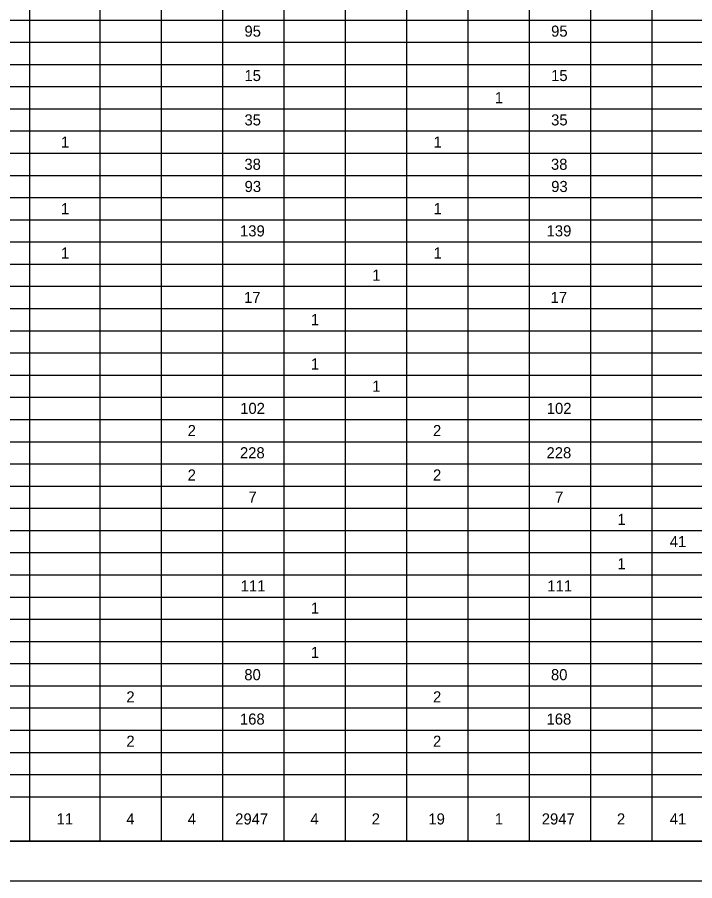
# Model space of a CAD drawing. Extents: x 0 to 34, y 0 to 22.
# Drawn here: x 17.13 to 25.68, y 0 to 10.89 of the extents above; entities that cross this region are included whole.
import ezdxf

# ---------------------------------------------------------------- set-up
doc = ezdxf.new("R2010")
doc.units = 0
for name, color, linetype in [('Default', 7, 'Continuous'), ('SH_Border', 7, 'Continuous'), ('SH_Cut_Line', 7, 'Continuous')]:
    doc.layers.add(name, color=color, linetype=linetype)

msp = doc.modelspace()

# ---------------------------------------------------------------- linework, layer by layer
at = {"layer": 'Default'}
for p, q in [((17.279, 21.5), (17.279, 0.5)), ((18.168, 21.5), (18.168, 0.5)), ((18.942, 21.5), (18.942, 0.5)), ((19.716, 21.5), (19.716, 0.5)), ((20.491, 21.5), (20.491, 0.5)), ((21.265, 21.5), (21.265, 0.5)), ((22.039, 21.5), (22.039, 0.5)), ((22.813, 21.5), (22.813, 0.5)), ((23.587, 21.5), (23.587, 0.5)), ((24.361, 21.5), (24.361, 0.5)), ((25.135, 21.5), (25.135, 0.5)), ((1.5, 10.86), (31.724, 10.86)), ((1.5, 10.58), (31.724, 10.58)), ((1.5, 10.3), (31.724, 10.3)), ((1.5, 10.02), (31.724, 10.02)), ((1.5, 9.74), (31.724, 9.74)), ((1.5, 9.46), (31.724, 9.46)), ((1.5, 9.18), (31.724, 9.18)), ((1.5, 8.9), (31.724, 8.9)), ((1.5, 8.62), (31.724, 8.62)), ((1.5, 8.34), (31.724, 8.34)), ((1.5, 8.06), (31.724, 8.06)), ((1.5, 7.78), (31.724, 7.78)), ((1.5, 7.5), (31.724, 7.5)), ((1.5, 7.22), (31.724, 7.22)), ((1.5, 6.94), (31.724, 6.94)), ((1.5, 6.66), (31.724, 6.66)), ((1.5, 6.38), (31.724, 6.38)), ((1.5, 6.1), (31.724, 6.1)), ((1.5, 5.82), (31.724, 5.82)), ((1.5, 5.54), (31.724, 5.54)), ((1.5, 5.26), (31.724, 5.26)), ((1.5, 4.98), (31.724, 4.98)), ((1.5, 4.7), (31.724, 4.7)), ((1.5, 4.42), (31.724, 4.42)), ((1.5, 4.14), (31.724, 4.14)), ((1.5, 3.86), (31.724, 3.86)), ((1.5, 3.58), (31.724, 3.58)), ((1.5, 3.3), (31.724, 3.3)), ((1.5, 3.02), (31.724, 3.02)), ((1.5, 2.74), (31.724, 2.74)), ((1.5, 2.46), (31.724, 2.46)), ((1.5, 2.18), (31.724, 2.18)), ((1.5, 1.9), (31.724, 1.9)), ((1.5, 1.62), (31.724, 1.62)), ((1.5, 1.34), (31.724, 1.34)), ((1.5, 1.06), (31.724, 1.06)), ((1.5, 0.5), (31.724, 0.5))]:
    msp.add_line(p, q, dxfattribs=at)
at = {"layer": 'SH_Border'}
msp.add_lwpolyline([(1.5, 21.5), (33.5, 21.5), (33.5, 0.5), (1.5, 0.5)], close=True, dxfattribs=at)
at = {"layer": 'SH_Cut_Line'}
msp.add_lwpolyline([(0, 0), (34, 0), (34, 22), (0, 22)], close=True, dxfattribs=at)

# ---------------------------------------------------------------- texts
at = {"layer": 'Default'}
for s, p in [('95', (19.994, 10.65)), ('95', (23.865, 10.65)), ('15', (19.994, 10.09)), ('15', (23.865, 10.09)), ('1', (23.154, 9.81)), ('35', (19.994, 9.53)), ('35', (23.865, 9.53)), ('1', (17.678, 9.25)), ('1', (22.38, 9.25)), ('38', (19.993, 8.97)), ('38', (23.863, 8.97)), ('93', (19.996, 8.69)), ('93', (23.866, 8.69)), ('1', (17.678, 8.41)), ('1', (22.38, 8.41)), ('139', (19.938, 8.13)), ('139', (23.808, 8.13)), ('1', (17.678, 7.85)), ('1', (22.38, 7.85)), ('1', (21.606, 7.57)), ('17', (19.989, 7.29)), ('17', (23.859, 7.29)), ('1', (20.832, 7.01)), ('1', (20.832, 6.45)), ('1', (21.606, 6.17)), ('102', (19.94, 5.89)), ('102', (23.81, 5.89)), ('2', (19.277, 5.61)), ('2', (22.374, 5.61)), ('228', (19.937, 5.33)), ('228', (23.807, 5.33)), ('2', (19.277, 5.05)), ('2', (22.374, 5.05)), ('7', (20.044, 4.77)), ('7', (23.915, 4.77)), ('1', (24.702, 4.49)), ('41', (25.363, 4.21)), ('1', (24.702, 3.93)), ('111', (19.946, 3.65)), ('111', (23.817, 3.65)), ('1', (20.832, 3.37)), ('1', (20.832, 2.81)), ('80', (19.992, 2.53)), ('80', (23.863, 2.53)), ('2', (18.503, 2.25)), ('2', (22.374, 2.25)), ('168', (19.937, 1.97)), ('168', (23.807, 1.97)), ('2', (18.503, 1.69)), ('2', (22.374, 1.69)), ('11', (17.622, 0.71)), ('4', (18.503, 0.71)), ('4', (19.278, 0.71)), ('2947', (19.877, 0.71)), ('4', (20.826, 0.71)), ('2', (21.6, 0.71)), ('19', (22.316, 0.71)), ('1', (23.154, 0.71)), ('2947', (23.747, 0.71)), ('2', (24.696, 0.71)), ('41', (25.363, 0.71))]:
    msp.add_text(s, height=0.14, dxfattribs=at).set_placement(p)

doc.saveas('drawing.dxf')
